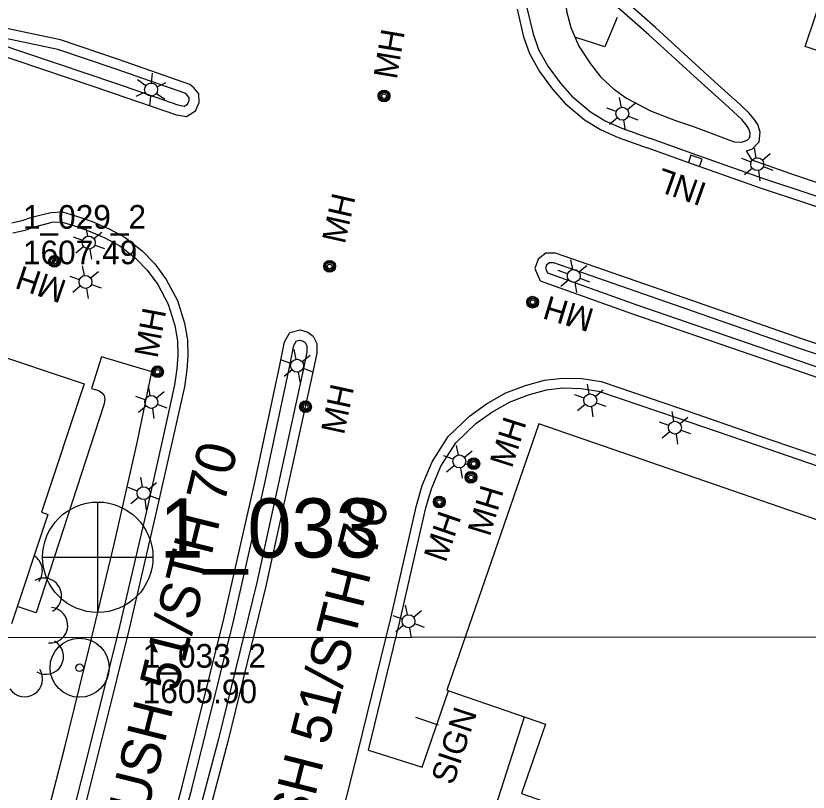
# Model space of a CAD drawing. Extents: x 189384 to 193282, y 256970 to 260388.
# Drawn here: x 190859 to 191059.9, y 258972.4 to 259169.2 of the extents above; entities that cross this region are included whole.
import ezdxf

# ---------------------------------------------------------------- set-up
doc = ezdxf.new("R2010")
doc.units = 0
for name, color, linetype in [('E_BLD', 7, 'Continuous'), ('E_DRN_Grate', 7, 'Continuous'), ('E_DWY', 7, 'Continuous'), ('E_LAND_Vegetation', 7, 'Continuous'), ('E_MAP_GridLines', 7, 'Continuous'), ('E_MAP_Limits', 7, 'Continuous'), ('E_MAP_PassPoints', 7, 'Continuous'), ('E_MISCPROP', 7, 'Continuous'), ('E_MISCPROP_HvyLine', 7, 'Continuous'), ('E_MISCPROP_Railing', 7, 'Continuous'), ('E_PATH_Sidewalk', 7, 'Continuous'), ('E_RDWY', 7, 'Continuous'), ('E_RDWY_Name', 7, 'Continuous')]:
    doc.layers.add(name, color=color, linetype=linetype)

# ---------------------------------------------------------------- blocks, each defined once
blk = doc.blocks.new('INLT')
at = {"layer": 'E_MISCPROP_Railing'}
blk.add_lwpolyline([(3, -2), (3, 0), (0, 0), (0, -2), (3, -2)], dxfattribs=at)
blk = doc.blocks.new('INL_4')
at = {"layer": 'E_MISCPROP_Railing'}
blk.add_text('INL', height=6, rotation=360, dxfattribs=at).set_placement((-5.79, -2.75))
blk = doc.blocks.new('MHO_3')
at = {"layer": 'E_DRN_Grate'}
for centre, radius in [((0.04, -0.06), 1.5), ((0.04, -0.06), 1.22), ((0.04, -0.07), 0.968), ((0.01, -0.08), 0.605)]:
    blk.add_circle(centre, radius, dxfattribs=at)
blk = doc.blocks.new('MHT_3')
at = {"layer": 'E_DRN_Grate'}
blk.add_text('MH', height=6, rotation=359.9999, dxfattribs=at).set_placement((-5.61, -3.06))
blk = doc.blocks.new('MHO_4')
at = {"layer": 'E_DRN_Grate'}
for centre, radius in [((0.04, -0.06), 1.5), ((0.04, -0.06), 1.22), ((0.04, -0.07), 0.968), ((0.01, -0.08), 0.605)]:
    blk.add_circle(centre, radius, dxfattribs=at)
blk = doc.blocks.new('MHT_4')
at = {"layer": 'E_DRN_Grate'}
blk.add_text('MH', height=6, rotation=0, dxfattribs=at).set_placement((-5.61, -3.06))
blk = doc.blocks.new('MHO_5')
at = {"layer": 'E_DRN_Grate'}
for centre, radius in [((0.04, -0.06), 1.5), ((0.04, -0.06), 1.22), ((0.04, -0.07), 0.968), ((0.01, -0.08), 0.605)]:
    blk.add_circle(centre, radius, dxfattribs=at)
blk = doc.blocks.new('MHT_5')
at = {"layer": 'E_DRN_Grate'}
blk.add_text('MH', height=6, rotation=0.0001, dxfattribs=at).set_placement((-5.61, -3.06))
blk = doc.blocks.new('MHO_6')
at = {"layer": 'E_DRN_Grate'}
for centre, radius in [((0.04, -0.06), 1.5), ((0.04, -0.06), 1.22), ((0.04, -0.07), 0.968), ((0.01, -0.08), 0.605)]:
    blk.add_circle(centre, radius, dxfattribs=at)
blk = doc.blocks.new('MHT_6')
at = {"layer": 'E_DRN_Grate'}
blk.add_text('MH', height=6, rotation=0.0001, dxfattribs=at).set_placement((-5.61, -3.06))
blk = doc.blocks.new('MHO_7')
at = {"layer": 'E_DRN_Grate'}
for centre, radius in [((0.04, -0.06), 1.5), ((0.04, -0.06), 1.22), ((0.04, -0.07), 0.968), ((0.01, -0.08), 0.605)]:
    blk.add_circle(centre, radius, dxfattribs=at)
blk = doc.blocks.new('MHT_7')
at = {"layer": 'E_DRN_Grate'}
blk.add_text('MH', height=6, rotation=360, dxfattribs=at).set_placement((-5.61, -3.06))
blk = doc.blocks.new('MHO_8')
at = {"layer": 'E_DRN_Grate'}
for centre, radius in [((0.04, -0.06), 1.5), ((0.04, -0.06), 1.22), ((0.04, -0.07), 0.968), ((0.01, -0.08), 0.605)]:
    blk.add_circle(centre, radius, dxfattribs=at)
blk = doc.blocks.new('MHT_8')
at = {"layer": 'E_DRN_Grate'}
blk.add_text('MH', height=6, rotation=359.9999, dxfattribs=at).set_placement((-5.61, -3.06))
blk = doc.blocks.new('MHO_9')
at = {"layer": 'E_DRN_Grate'}
for centre, radius in [((0.04, -0.06), 1.5), ((0.04, -0.06), 1.22), ((0.04, -0.07), 0.968), ((0.01, -0.08), 0.605)]:
    blk.add_circle(centre, radius, dxfattribs=at)
blk = doc.blocks.new('MHT_9')
at = {"layer": 'E_DRN_Grate'}
blk.add_text('MH', height=6, rotation=360, dxfattribs=at).set_placement((-5.61, -3.06))
blk = doc.blocks.new('MHO_11')
at = {"layer": 'E_DRN_Grate'}
for centre, radius in [((0.04, -0.06), 1.5), ((0.04, -0.06), 1.22), ((0.04, -0.07), 0.968), ((0.01, -0.08), 0.605)]:
    blk.add_circle(centre, radius, dxfattribs=at)
blk = doc.blocks.new('MHT_11')
at = {"layer": 'E_DRN_Grate'}
blk.add_text('MH', height=6, rotation=0.0001, dxfattribs=at).set_placement((-5.61, -3.06))
blk = doc.blocks.new('LTP')
at = {"layer": 'E_MISCPROP'}
for p, q in [((-0.78, 1.46), (-1.98, 3.76)), ((0.86, 1.37), (2.22, 3.6)), ((-1.61, 0.09), (-4.22, 0.17)), ((1.66, 0), (4.18, -0.06)), ((-0.86, -1.4), (-2.22, -3.59)), ((0.78, -1.44), (2.02, -3.62))]:
    blk.add_line(p, q, dxfattribs=at)
blk.add_circle((0.02, 0.01), 1.64, dxfattribs=at)
blk = doc.blocks.new('SIGN')
at = {"layer": 'E_MISCPROP'}
blk.add_text('SIGN', height=6, rotation=0, dxfattribs=at).set_placement((0, -3))
blk = doc.blocks.new('MHO_14')
at = {"layer": 'E_DRN_Grate'}
for centre, radius in [((0.04, -0.06), 1.5), ((0.04, -0.06), 1.22), ((0.04, -0.07), 0.968), ((0.01, -0.08), 0.605)]:
    blk.add_circle(centre, radius, dxfattribs=at)
blk = doc.blocks.new('MHT_12')
at = {"layer": 'E_DRN_Grate'}
blk.add_text('MH', height=6, rotation=0.0001, dxfattribs=at).set_placement((-5.61, -3.06))
blk = doc.blocks.new('LTP_1')
at = {"layer": 'E_MISCPROP'}
for p, q in [((-0.78, 1.46), (-1.98, 3.76)), ((0.86, 1.37), (2.22, 3.6)), ((-1.61, 0.09), (-4.22, 0.17)), ((1.66, 0), (4.18, -0.07)), ((-0.86, -1.4), (-2.22, -3.59)), ((0.78, -1.44), (2.02, -3.62))]:
    blk.add_line(p, q, dxfattribs=at)
blk.add_circle((0.02, 0.01), 1.64, dxfattribs=at)
blk = doc.blocks.new('PP_7')
at = {"layer": 'E_MAP_PassPoints'}
for radius in [7.5, 0.96]:
    blk.add_circle((0, 0), radius, dxfattribs=at)
blk = doc.blocks.new('PHOTOC_1')
at = {"layer": 'E_MAP_Limits'}
for p, q in [((0.12, 14.06), (0.06, -13.8)), ((-13.79, 0.03), (14.12, 0.01))]:
    blk.add_line(p, q, dxfattribs=at)
blk.add_circle((0.17, 0.03), 14, dxfattribs=at)

msp = doc.modelspace()

# ---------------------------------------------------------------- linework, layer by layer
at = {"layer": 'E_BLD'}
msp.add_lwpolyline([(191149, 259011.4), (190991.59, 259065.79), (190991.59, 259065.79), (190991.59, 259065.79), (190968.26, 258998.26), (190968.26, 258998.26), (190993.29, 258989.61), (190993.29, 258989.61), (190987.21, 258972.02), (190987.21, 258972.02), (191003.44, 258966.42), (191003.44, 258966.42), (191002.18, 258962.75), (191002.18, 258962.75), (191012.04, 258959.34), (191013.5, 258963.56), (191013.5, 258963.56), (191013.5, 258963.56), (191024.21, 258959.86), (191025.43, 258963.38), (191025.43, 258963.38), (191060.5, 258951.26)], dxfattribs=at)
at = {"layer": 'E_DWY'}
for points in [[(191041.42, 259147.83), (191034.49, 259154.01), (191021.16, 259166.18), (191008.62, 259177.39), (191003.17, 259182.4), (191001.43, 259183.06), (190999.35, 259182.89), (190998.05, 259182.13)], [(191039.75, 259145.97), (191032.82, 259152.15), (191019.49, 259164.33), (191006.94, 259175.54), (191001.83, 259180.24), (191001.07, 259180.52), (191000.12, 259180.44), (190999.48, 259180.07), (190998.81, 259179.24), (190998.54, 259177.81), (190998.31, 259174.49), (190998.63, 259170.35), (190999.68, 259166.21), (191001.78, 259161.45), (191004.72, 259156.99), (191007.35, 259153.66), (191010.51, 259150.69), (191013.82, 259148.31), (191019.89, 259145.1), (191026.22, 259142.62), (191030.57, 259141.21)], [(191044.27, 259134.92), (191045.82, 259135.46), (191047.51, 259137.27), (191047.75, 259139.66), (191047.15, 259141.66), (191046.15, 259143.05), (191044.89, 259144.61), (191041.45, 259147.8)], [(191030.57, 259141.21), (191041.11, 259137.22), (191043.04, 259137.13), (191044.41, 259137.62), (191045.11, 259138.36), (191045.21, 259139.42), (191044.88, 259140.53), (191044.15, 259141.54), (191043.06, 259142.91), (191039.75, 259145.97)], [(191055.29, 259129.19), (191045.66, 259132.58), (191044.27, 259134.92)], [(191156.55, 259084.39), (191157.52, 259086.27), (191157.48, 259086.8), (191157.17, 259087.48), (191105.87, 259111.44), (191096.79, 259115.21), (191055.29, 259129.19)], [(190948.39, 258983.05), (190962.01, 258978.74), (190968.73, 258998.1)], [(190952.89, 258916.41), (190952.09, 258918.7), (190952.11, 258920.36), (190952.45, 258921.78), (190953.5, 258923.12), (190954.84, 258924.04), (190956.61, 258924.37), (190958.87, 258924.04), (190962.47, 258923.05), (190963.8, 258922.88), (190965.22, 258923.23), (190966.3, 258924.13), (190987.99, 258991.45)]]:
    msp.add_lwpolyline(points, dxfattribs=at)
at = {"layer": 'E_LAND_Vegetation'}
for centre, start, end in [((190861.2, 259028.53), 322.9759, 57.2776), ((190866.07, 259022.16), 299.8716, 119.8716), ((190867.64, 259014.7), 265.1696, 85.1696), ((190866.55, 259006.77), 240.0665, 60.0665), ((190861.25, 259001.07), 212.9287, 32.9287)]:
    msp.add_arc(centre, 4.51, start, end, dxfattribs=at)
at = {"layer": 'E_MAP_GridLines'}
msp.add_line((190146.69, 259011.09), (191646.69, 259012.15), dxfattribs=at)
msp.add_line((190146.69, 259011.09), (191646.69, 259012.15), dxfattribs=at)
msp.add_line((190146.69, 259011.09), (191646.69, 259012.15), dxfattribs=at)
at = {"layer": 'E_MISCPROP'}
for p, q in [((191011.48, 259168.72), (191008.35, 259161.33)), ((191008.35, 259161.33), (191000.72, 259163.76)), ((190960.32, 258991.44), (190966.06, 258989.48))]:
    msp.add_line(p, q, dxfattribs=at)
at = {"layer": 'E_MISCPROP_HvyLine'}
msp.add_lwpolyline([(191070.49, 259195.86), (191104.88, 259184.44), (191104.88, 259184.44), (191104.88, 259184.44), (191093.43, 259149.98), (191093.43, 259149.98), (191059.17, 259161.37), (191064.72, 259178.06), (191064.72, 259178.06), (191064.72, 259178.06), (191054.38, 259181.5), (191056.93, 259189.19), (191056.93, 259189.19), (191067.14, 259185.8), (191067.14, 259185.8), (191067.14, 259185.8)], close=True, dxfattribs=at)
msp.add_lwpolyline([(190826.18, 259092.6), (190876.32, 259075.92), (190876.32, 259075.92), (190876.32, 259075.92), (190865.49, 259043.36), (190867.13, 259042.81), (190867.13, 259042.81), (190857.89, 259015.03)], dxfattribs=at)
at = {"layer": 'E_PATH_Sidewalk'}
msp.add_lwpolyline([(190860.35, 258942.51), (190862.73, 258950.26), (190866.12, 258963.21), (190871.2, 258983.09), (190877.77, 259009.54), (190884.02, 259035.63), (190889.84, 259061.37), (190893.46, 259078.93), (190880.74, 259082.73), (190878.16, 259074.73), (190879.99, 259074.2), (190880.82, 259073.64), (190881.39, 259072.93), (190881.58, 259071.94), (190881.32, 259070.61), (190864.15, 259017.83), (190859.35, 259019.44)], dxfattribs=at)
at = {"layer": 'E_RDWY'}
for points in [[(190991.43, 259196.39), (190991.09, 259193.83), (190990.44, 259189.67), (190989.05, 259180.68), (190988.41, 259175.87), (190988.59, 259171.21), (190990.15, 259164.57), (190991.53, 259160.66), (190993.85, 259156.44), (190997.01, 259152.17), (190999.96, 259148.83), (191004.67, 259144.82), (191008.44, 259142.6), (191012.62, 259140.68), (191019.96, 259138.05)], [(190885, 259158.07), (190870.33, 259163.06), (190830.41, 259171.44), (190792.55, 259179.35), (190762.5, 259185.57), (190760.73, 259185.83), (190759.01, 259184.36), (190758.47, 259182.46), (190759.39, 259180.13), (190761.09, 259179.61), (190795.96, 259172.03), (190846.93, 259161.35), (190853.15, 259159.91), (190883.71, 259149.61)], [(190884.2, 259155.71), (190869.67, 259160.64), (190829.9, 259169), (190792.04, 259176.9), (190762.07, 259183.11), (190761.49, 259183.19), (190761.21, 259182.95), (190761.11, 259182.59), (190761.27, 259182.17), (190761.72, 259182.03), (190796.49, 259174.48), (190847.46, 259163.79), (190853.84, 259162.32), (190884.51, 259151.98)], [(190986.1, 259170.87), (190987.75, 259163.86), (190989.24, 259159.64), (190991.74, 259155.09), (190995.07, 259150.59), (190998.2, 259147.05), (191003.21, 259142.77), (191007.28, 259140.38), (191011.68, 259138.36), (191019.11, 259135.7)], [(190883.69, 259149.61), (190899.72, 259144.07), (190902.24, 259143.62), (190904.5, 259145.13), (190905.43, 259147.22), (190905.38, 259149.4), (190904.09, 259150.92), (190903.06, 259151.8), (190885.02, 259158.07)], [(190884.51, 259151.98), (190900.35, 259146.5), (190901.69, 259146.26), (190902.51, 259146.81), (190902.92, 259147.72), (190902.9, 259148.46), (190902.31, 259149.15), (190901.8, 259149.59), (190884.2, 259155.71)], [(191156.55, 259084.39), (191124.19, 259099.2), (191103.22, 259108.93), (191094.59, 259112.39), (191082.86, 259116.52), (191048.39, 259127.94), (191030.48, 259134.28), (191019.96, 259138.05)], [(191323.95, 259009.02), (191290.29, 259020.88), (191281.26, 259024.23), (191271.02, 259028.89), (191236.38, 259044.94), (191196.97, 259062.95), (191160.57, 259079.8), (191123.15, 259096.93), (191102.22, 259106.64), (191093.71, 259110.05), (191082.05, 259114.15), (191047.58, 259125.57), (191029.64, 259131.93), (191019.11, 259135.7)], [(191323.95, 259009.02), (191290.29, 259020.88), (191281.26, 259024.23), (191271.02, 259028.89), (191236.38, 259044.94), (191196.97, 259062.95), (191160.57, 259079.8), (191123.15, 259096.93), (191102.22, 259106.64), (191093.71, 259110.05), (191082.05, 259114.15), (191047.58, 259125.57), (191029.64, 259131.93), (191019.11, 259135.7)], [(191323.95, 259009.02), (191290.29, 259020.88), (191281.26, 259024.23), (191271.02, 259028.89), (191236.38, 259044.94), (191196.97, 259062.95), (191160.57, 259079.8), (191123.15, 259096.93), (191102.22, 259106.64), (191093.71, 259110.05), (191082.05, 259114.15), (191047.58, 259125.57), (191029.64, 259131.93), (191019.11, 259135.7)], [(190858, 259116.68), (190860.61, 259117.28), (190863, 259118.13), (190865.41, 259118.73), (190867.85, 259119.35), (190870.81, 259119.49), (190874.09, 259118.51), (190878.32, 259117.01), (190882.63, 259115.19), (190886.7, 259112.95), (190891.02, 259109.58), (190894.21, 259106.32), (190897.14, 259102.38), (190899.95, 259097.04), (190901.72, 259091.24), (190902.51, 259087.07), (190902.56, 259083.11), (190902.31, 259079.46), (190901.71, 259075.17), (190899.78, 259066.55), (190894.77, 259044.14), (190887.72, 259013.81), (190881.35, 258988.26), (190874.58, 258961.35)], [(190858.19, 259114.16), (190861.31, 259114.88), (190863.73, 259115.73), (190866.02, 259116.3), (190868.22, 259116.87), (190870.5, 259116.97), (190873.31, 259116.13), (190877.42, 259114.67), (190881.54, 259112.94), (190885.32, 259110.86), (190889.35, 259107.72), (190892.3, 259104.69), (190895.01, 259101.04), (190897.63, 259096.08), (190899.29, 259090.64), (190900.01, 259086.82), (190900.06, 259083.18), (190899.82, 259079.71), (190899.25, 259075.62), (190897.34, 259067.1), (190892.33, 259044.7), (190885.29, 259014.39), (190878.92, 258988.87), (190872.16, 258961.98)], [(191099.03, 259074.97), (191091.57, 259076.79), (191085.63, 259078.26), (191080.37, 259079.85), (191058.29, 259087.3), (191024.59, 259099.07), (190995.87, 259109.02), (190993.35, 259109.04), (190991.44, 259107.53), (190990.56, 259105.13), (190991.9, 259102.02), (191015.33, 259093.63), (191056.65, 259079.42), (191096.25, 259065.71), (191134.87, 259052.25)], [(191098.44, 259072.54), (191090.97, 259074.36), (191084.97, 259075.85), (191079.61, 259077.47), (191057.47, 259084.93), (191023.77, 259096.71), (190995.44, 259106.53), (190994.21, 259106.53), (190993.55, 259106.01), (190993.25, 259105.2), (190993.77, 259104.01), (191016.16, 259095.99), (191057.46, 259081.78), (191097.07, 259068.07), (191135.7, 259054.61)], [(190883.66, 258910.77), (190891.68, 258938.26), (190901.24, 258974.18), (190911.75, 259016.33), (190919.67, 259051.27), (190925.91, 259080.64), (190927.07, 259086.53), (190928.48, 259088.93), (190931.06, 259089.6), (190933.04, 259089.01), (190934.38, 259087.95), (190935.27, 259086.08), (190935.3, 259083.64), (190934.37, 259079.28), (190922.5, 259025)], [(190886.06, 258910.07), (190894.09, 258937.59), (190903.66, 258973.55), (190914.18, 259015.75), (190922.12, 259050.73), (190928.36, 259080.14), (190929.44, 259085.63), (190930.11, 259086.77), (190931.02, 259087), (190931.86, 259086.75), (190932.37, 259086.35), (190932.78, 259085.5), (190932.79, 259083.89), (190931.93, 259079.8), (190920.06, 259025.54)], [(190892.43, 258801.6), (190908.33, 258850.2), (190920.04, 258888.14), (190923.17, 258899), (190934.52, 258938.19), (190945.68, 258982.48), (190953.95, 259016.19), (190960.55, 259045.06), (190962.04, 259050.13), (190964.56, 259056.16), (190968.64, 259062.58), (190974.04, 259067.74), (190978.3, 259070.86), (190983.25, 259073.61), (190988.22, 259075.46), (190993.06, 259076.81), (190997.59, 259077.34), (191002.53, 259077.24), (191007.37, 259076.47), (191027.53, 259069.66), (191047.5, 259062.75), (191084.14, 259050.2)], [(190948.39, 258983.05), (190956.38, 259015.62), (190962.97, 259044.43), (190964.4, 259049.29), (190966.78, 259055), (190970.59, 259060.98), (190975.65, 259065.82), (190979.66, 259068.75), (190984.3, 259071.33), (190988.99, 259073.08), (190993.55, 259074.35), (190997.71, 259074.84), (191002.31, 259074.75), (191006.77, 259074.03), (191026.72, 259067.3), (191046.68, 259060.39), (191083.32, 259047.84)], [(190922.48, 259024.94), (190912.75, 258985.27), (190902.75, 258947.42), (190895.59, 258909.08), (190888.92, 258872.77), (190887.15, 258863.58), (190885.34, 258855.91), (190882.91, 258847.73), (190880.82, 258841.4), (190879.77, 258839.09), (190877.63, 258838.08), (190875.7, 258837.8), (190873.19, 258838.49), (190872.18, 258840.65), (190871.31, 258847.41), (190870.72, 258856.44), (190870.68, 258861.15), (190870.94, 258865.06), (190871.66, 258869.3), (190872.66, 258874.12), (190875.36, 258882.71), (190883.66, 258910.78)], [(190920.06, 259025.54), (190910.33, 258985.89), (190900.31, 258947.97), (190893.13, 258909.53), (190886.47, 258873.23), (190884.7, 258864.11), (190882.93, 258856.56), (190880.53, 258848.48), (190878.48, 258842.31), (190877.87, 258840.96), (190876.9, 258840.5), (190875.86, 258840.35), (190874.97, 258840.59), (190874.61, 258841.36), (190873.8, 258847.65), (190873.22, 258856.53), (190873.18, 258861.08), (190873.42, 258864.77), (190874.12, 258868.84), (190875.08, 258873.49), (190877.76, 258881.98), (190886.06, 258910.07)]]:
    msp.add_lwpolyline(points, dxfattribs=at)

# ---------------------------------------------------------------- block references
at = {"layer": 'E_DRN_Grate'}
for name, p, rotation in [('MHT_12', (190953.48, 259158.92), 80.43807343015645), ('MHO_14', (190952.29, 259148.84), 80.43807345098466), ('MHO_5', (190974.32, 259052.17), 73.20615189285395), ('MHT_5', (190977.86, 259043.21), 73.20615182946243)]:
    msp.add_blockref(name, p, dxfattribs=dict(at, rotation=rotation))
for name, p, xscale, yscale, rotation in [('MHT_11', (190940.66, 259117.28), 0.9999986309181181, 0.999998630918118, 77.12550676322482), ('MHO_9', (190868.79, 259106.86), 1.0000011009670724, 1.0000011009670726, 161.2438105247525), ('MHO_11', (190938.48, 259105.67), 0.9999986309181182, 0.9999986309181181, 77.12550680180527), ('MHT_9', (190865.9, 259100.83), 1.0000011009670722, 1.0000011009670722, 161.2438105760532), ('MHO_3', (190990.04, 259096.52), 0.9999982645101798, 0.9999982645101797, 163.20834912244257), ('MHT_3', (190999.7, 259093.4), 0.9999982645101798, 0.9999982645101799, 163.20834895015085), ('MHT_8', (190892.88, 259088.26), 0.9999975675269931, 0.9999975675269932, 79.49176278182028), ('MHO_8', (190894.84, 259078.93), 0.9999975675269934, 0.9999975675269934, 79.49176274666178), ('MHT_7', (190940.36, 259068.91), 0.9999989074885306, 0.9999989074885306, 77.86487624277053), ('MHO_7', (190932.37, 259070.06), 0.9999989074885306, 0.9999989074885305, 77.86487638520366), ('MHT_4', (190983.56, 259060.55), 1.000001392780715, 1.000001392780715, 72.3333125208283), ('MHO_4', (190975.03, 259055.63), 1.0000013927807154, 1.0000013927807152, 72.33331267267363), ('MHO_6', (190966.28, 259045.94), 1.0000010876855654, 1.0000010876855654, 70.99532713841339), ('MHT_6', (190966.89, 259036.66), 1.000001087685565, 1.0000010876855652, 70.99532712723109)]:
    msp.add_blockref(name, p, dxfattribs=dict(at, xscale=xscale, yscale=yscale, rotation=rotation))
at = {"layer": 'E_MAP_Limits', "rotation": -0.0001081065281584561}
msp.add_blockref('PHOTOC_1', (190879.59, 259031.91), dxfattribs=at)
at = {"layer": 'E_MAP_PassPoints', "rotation": -0.00010802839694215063}
msp.add_blockref('PP_7', (190875.15, 259003.94), dxfattribs=at)
at = {"layer": 'E_MISCPROP'}
for name, p, xscale, yscale, rotation in [('LTP_1', (190893.29, 259150.47), 1.0000014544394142, 1.000001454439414, 86.2723201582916), ('SIGN', (190967.02, 258974.9), 0.9999982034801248, 0.9999982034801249, 71.76379010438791)]:
    msp.add_blockref(name, p, dxfattribs=dict(at, xscale=xscale, yscale=yscale, rotation=rotation))
for p, rotation in [((191012.8, 259144.36), 161.13015640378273), ((191047.02, 259131.58), 161.13015579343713), ((190877.5, 259111.69), 161.13015881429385), ((191000.47, 259103.25), 161.13015662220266), ((190876.66, 259101.72), 161.13015882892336), ((190930.32, 259080.48), 161.13015787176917), ((190893.35, 259071.31), 161.13015853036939), ((191004.67, 259071.72), 161.1301565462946), ((191026.14, 259064.79), 161.13015616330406), ((190971.47, 259056.22), 161.13015713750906), ((190891.4, 259048.18), 161.1301585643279), ((190958.57, 259015.72), 161.13015736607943)]:
    msp.add_blockref('LTP', p, dxfattribs=dict(at, rotation=rotation))
at = {"layer": 'E_MISCPROP_Railing'}
for name, p, xscale, yscale, rotation in [('INLT', (191032.34, 259130.97), 1.0000021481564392, 1.0000021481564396, 160.49216450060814), ('INL_4', (191028.19, 259125.88), 1.0000021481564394, 1.0000021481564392, 160.4921645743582)]:
    msp.add_blockref(name, p, dxfattribs=dict(at, xscale=xscale, yscale=yscale, rotation=rotation))

# ---------------------------------------------------------------- texts
at = {"layer": 'E_MAP_Limits'}
msp.add_text('1_033', height=15, rotation=0, dxfattribs=at).set_placement((190895.41, 259031.87))
at = {"layer": 'E_MAP_PassPoints'}
for s, rotation, p in [('1_029_2', 0.0407, (190860.77, 259115.2)), ('1_029_2', 0.0407, (190860.77, 259115.2)), ('1607.49', 0.0407, (190860.78, 259106.2)), ('1607.49', 0.0407, (190860.78, 259106.2)), ('1_033_2', 0, (190891.15, 259003.94)), ('1605.90', 0, (190891.15, 258994.94))]:
    msp.add_text(s, height=6, rotation=rotation, dxfattribs=at).set_placement(p)
at = {"layer": 'E_RDWY_Name'}
for rotation, p in [(76.0003, (190892.18, 258966.5)), (75.863, (190930.29, 258953.03))]:
    msp.add_text('USH 51/STH 70', height=10, rotation=rotation, dxfattribs=at).set_placement(p)

doc.saveas('drawing.dxf')
